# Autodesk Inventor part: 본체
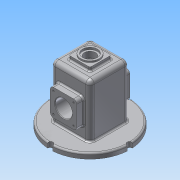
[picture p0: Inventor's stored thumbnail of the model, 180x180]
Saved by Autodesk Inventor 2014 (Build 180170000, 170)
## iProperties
Created: 2018-07
Part Number: 본체
Material: 알루미늄 6061
Document SubType Name: Modeling
Designer: user
Density: 2.71 g/cm^3
Appearance: 알루미늄 - 평지
Mass: 924.652 g
Surface Area: 1023.59 cm^2
Volume: 341.2 cm^3
Author: user
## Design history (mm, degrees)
sketch "스케치1"
  geometry: A1 r 5 centre (0, 75) between (4.997, 74.833) and (-4.997, 74.833); A2 r 5 centre (75, 0) between (74.833, -4.997) and (74.833, 4.997); A3 r 5 centre (0, -75) between (-4.997, -74.833) and (4.997, -74.833); A4 r 5 centre (-75, 0) between (-74.833, 4.997) and (-74.833, -4.997); A5 r 75 centre (0, 0) between (74.833, 4.997) and (4.997, 74.833); A6 r 75 centre (0, 0) between (4.997, -74.833) and (74.833, -4.997); A7 r 75 centre (0, 0) between (-4.997, 74.833) and (-74.833, 4.997); A8 r 75 centre (0, 0) between (-74.833, -4.997) and (-4.997, -74.833); 1 further point
  constraints: 16 point on circle, 8 centre point, 2 horizontal alignment, 2 vertical alignment, 1 coincident
  dimensions: "d1" = 10 diameter of A1; "d2" = 10 diameter of A2; "d3" = 10 diameter of A3; "d4" = 10 diameter of A4; "d5" = 75 radius of A5; "d6" = 75 radius of A6; "d7" = 75 radius of A8; "d8" = 75 radius of A7; "d9" = 150 distance of A4.centre A2.centre; "d10" = 150 distance of A3.centre A1.centre; "d11" = 75 distance of A1.centre point (0, 0); "d12" = 75 distance of point (0, 0) A2.centre
extrude "돌출1" new body sketch "스케치1" distance "d13" = 10; taper "d14" = 0 deg
sketch "스케치2"
  geometry: L1 (-37, 37)-(37, 37); L2 (37, 37)-(37, -37); L3 (37, -37)-(-37, -37); L4 (-37, -37)-(-37, 37); L5 (-37, 37)-(37, -37); L6 (37, 37)-(-37, -37); A1 r 75 centre (0, 0) between (74.833, 4.997) and (4.997, 74.833) reference
  constraints: 12 end point, 2 midpoint, 2 parallel, 1 horizontal, 1 perpendicular
  dimensions: "d15" = 74 distance of L2.end L3.end; "d16" = 74 distance of L1.end L2.end
extrude "돌출2" join sketch "스케치2" distance "d17" = 100; taper "d18" = 0 deg
sketch "스케치3"
  geometry: L1 (-20, 20)-(20, 20); L2 (20, 20)-(20, -20); L3 (20, -20)-(-20, -20); L4 (-20, -20)-(-20, 20); L5 (-20, 20)-(20, -20); L6 (20, 20)-(-20, -20); 1 further point
  constraints: 12 end point, 2 midpoint, 2 parallel, 1 horizontal, 1 perpendicular
  dimensions: "d19" = 40 distance of L2.end L3.end; "d20" = 40 distance of L1.end L2.end
extrude "돌출3" join sketch "스케치3" distance "d21" = 7; taper "d22" = 0 deg
sketch "스케치4"
  geometry: C1 r 17.5 at (0, 0); 1 further point
  constraints: 1 centre point, 1 coincident
  dimensions: "d23" = 35 diameter of C1
extrude "돌출4" join sketch "스케치4" distance "d24" = 3; taper "d25" = 0 deg
sketch "스케치5"
  geometry: L1 (12, 70)-(62, 70); L2 (62, 70)-(62, 20); L3 (62, 20)-(12, 20); L4 (12, 20)-(12, 70); L5 (12, 70)-(62, 20); L6 (62, 70)-(12, 20); L7 (111.833, -10)-(41.997, -10) reference; 3 further points
  constraints: 12 end point, 3 midpoint, 2 parallel, 1 horizontal, 1 perpendicular, 1 vertical alignment
  dimensions: "d26" = 50 distance of L2.end L3.end; "d27" = 50 distance of L1.end L2.end; "d28" = 55 distance from line of point (37, 45) L7
extrude "돌출5" join sketch "스케치5" distance "d29" = 13; taper "d30" = 0 deg
sketch "스케치7"
  geometry: L1 (-32, 32)-(32, 32); L2 (32, 32)-(32, -32); L3 (32, -32)-(-32, -32); L4 (-32, -32)-(-32, 32); L5 (-32, 32)-(32, -32); L6 (32, 32)-(-32, -32); A1 r 75 centre (0, 0) between (74.833, 4.997) and (4.997, 74.833) reference
  constraints: 12 end point, 2 midpoint, 2 parallel, 1 horizontal, 1 perpendicular
  dimensions: "d38" = 64 distance of L2.end L3.end; "d39" = 64 distance of L1.end L2.end
extrude "돌출6" cut sketch "스케치7" distance "d40" = 105; taper "d41" = 0 deg
sketch "스케치9"
  geometry: L1 (64, 0)-(0, 0) reference; L2 (64, 105)-(0, 105) reference; C1 r 25 at (32, 55); 2 further points
  constraints: 1 centre point, 1 midpoint, 1 vertical alignment
  dimensions: "d45" = 50 diameter of C1; "d46" = 55 distance from line of C1.centre L1
extrude "돌출8" join sketch "스케치9" distance "d47" = 7; taper "d48" = -20 deg
sketch "스케치10"
  geometry: L1 (0, 50)-(50, 50) reference; L2 (0, 0)-(0, 50) reference; 4 further points
  constraints: 2 midpoint, 1 horizontal alignment, 1 vertical alignment
hole "구멍2" sketch "스케치10" at (25, 25) diameter "d49" = 32; stored, may be unused: countersink angle "d53" = 90 deg, drill point angle "d55" = 118 deg; dims "d50" = 6, "d51" = 4, "d52" = 2, "d54" = 8
sketch "스케치11"
  geometry: L1 (74, 0)-(74, -100) reference; L2 (19.5, -110)-(54.5, -110) reference; 2 further points
  constraints: 1 other
  dimensions: "d56" = 30 distance from line of point (37, -80) L2; "d57" = 37 distance from line of point (37, -80) L1
feature "엠보싱1" sketch "스케치11" dims "d2" = 10, "d15" = 74, "d16" = 74, "d58" = 0.5, "d59" = 0
hole "구멍3" diameter "d62" = 21; stored, may be unused: countersink angle "d66" = 90 deg, drill point angle "d68" = 118 deg; dims "d60" = 10, "d61" = 10, "d63" = 6, "d64" = 28, "d65" = 4, "d67" = 8
fillet "모깎기1" dims "d69" = 6
sketch "스케치12"
  geometry: A1 r 6 centre (38, -6) between (44, -6) and (38, 0) reference; A2 r 6 centre (0, -6) between (0, 0) and (-6, -6) reference; A3 r 6 centre (0, -44) between (-6, -44) and (0, -50) reference; A4 r 6 centre (38, -44) between (38, -50) and (44, -44) reference; 5 further points
  constraints: 4 coincident
hole "구멍4" sketch "스케치12" at (38, -44), (0, -44), (0, -6), (38, -6) diameter "d70" = 3.242; stored, may be unused: countersink angle "d74" = 90 deg, drill point angle "d76" = 118 deg; dims "d71" = 8, "d72" = 28, "d73" = 4, "d75" = 10
fillet "모깎기2" dims "d77" = 6
fillet "모깎기3" dims "d78" = 8
fillet "모깎기4" dims "d79" = 3
fillet "모깎기5" dims "d80" = 8
fillet "모깎기6" dims "d81" = 3
fillet "모깎기7" dims "d82" = 3
fillet "모깎기8" dims "d83" = 3
fillet "모깎기9" dims "d84" = 3
fillet "모깎기10" dims "d85" = 3
chamfer "모따기1" distance "d86" = 1; stored, may be unused: second distance "d87" = 2, angle "d88" = 45 deg
fillet "모깎기11" dims "d89" = 3
node "솔리드1"
mirror "대칭1"
mirror "대칭2"
mirror "대칭3"
